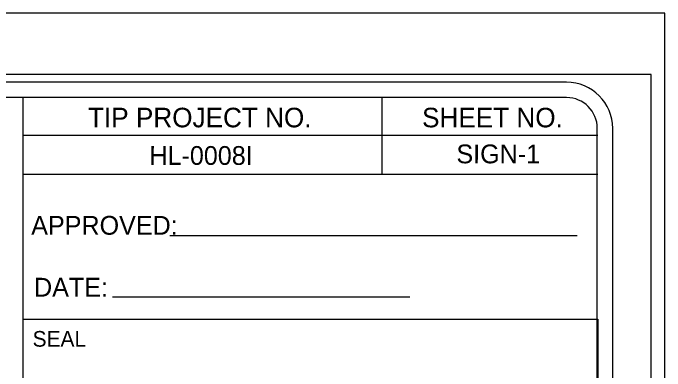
# Model space of a CAD drawing. Extents: x 2046816 to 2049224, y 578750 to 586986.
# Drawn here: x 2049012.1 to 2049224.2, y 586869.4 to 586985.8 of the extents above; entities that cross this region are included whole.
import ezdxf

# ---------------------------------------------------------------- set-up
doc = ezdxf.new("R2010")
doc.units = 0
for name, color, linetype in [('Default', 7, 'Continuous'), ('Old_Level_10', 7, 'Continuous'), ('Old_Level_2', 7, 'Continuous'), ('Old_Level_4', 7, 'Continuous'), ('Sheet Plot Border Inside CELL', 7, 'Continuous'), ('Sheet Plot Border Outside CELL', 7, 'Continuous'), ('Sheet Title CELL', 7, 'Continuous')]:
    doc.layers.add(name, color=color, linetype=linetype)

msp = doc.modelspace()

# ---------------------------------------------------------------- linework, layer by layer
at = {"layer": 'Default'}
for p, q in [((2049015.39, 586933.37), (2049015.39, 586958.31)), ((2049132.11, 586933.36), (2049132.12, 586958.32)), ((2049132.11, 586933.36), (2049132.12, 586958.32)), ((2049015.39, 586946.11), (2049132.12, 586946.1)), ((2049132.12, 586946.1), (2049202.34, 586946.09)), ((2049015.39, 586933.37), (2049202.33, 586933.36)), ((2049063.07, 586913.46), (2049195.65, 586913.46)), ((2049044.39, 586893.55), (2049141.15, 586893.55))]:
    msp.add_line(p, q, dxfattribs=at)
at = {"layer": 'Old_Level_2'}
msp.add_line((2049015.39, 586886.21), (2049015.39, 586933.37), dxfattribs=at)
msp.add_lwpolyline([(2049015.39, 586886.21), (2049202.33, 586886.21), (2049202.33, 586774.83), (2049015.39, 586774.83)], close=True, dxfattribs=at)
at = {"layer": 'Sheet Plot Border Inside CELL'}
msp.add_lwpolyline([(2047553.67, 585910.81), (2049219.66, 585910.81), (2049219.66, 586965.81), (2047553.67, 586965.81)], close=True, dxfattribs=at)
at = {"layer": 'Sheet Plot Border Outside CELL'}
msp.add_lwpolyline([(2049224.17, 586985.81), (2047540.67, 586985.81), (2047540.67, 585890.81), (2049224.17, 585890.81)], close=True, dxfattribs=at)
at = {"layer": 'Sheet Title CELL'}
for points in [[(2049192.16, 586963.31), (2047722.16, 586963.33)], [(2049192.16, 586958.31), (2047772.16, 586958.31)], [(2049202.16, 585928.31), (2049202.16, 586948.31)], [(2049207.16, 585928.31), (2049207.16, 586948.31)]]:
    msp.add_lwpolyline(points, dxfattribs=at)
for radius, end in [(15, 89.9995), (10, 90)]:
    msp.add_arc((2049192.16, 586948.31), radius, 360, end, dxfattribs=at)

# ---------------------------------------------------------------- texts
at = {"layer": 'Default'}
for s, height, p in [('TIP PROJECT NO.', 6.3564, (2049036.45, 586948.65)), ('SHEET NO.', 6.356, (2049145.14, 586948.64)), ('HL-0008I', 6.108, (2049056.43, 586936.43)), ('SIGN-1', 6.108, (2049156.32, 586936.94))]:
    msp.add_text(s, height=height, rotation=359.9949, dxfattribs=at).set_placement(p)
at = {"layer": 'Old_Level_10'}
msp.add_text('SEAL', height=5.093, rotation=359.9949, dxfattribs=at).set_placement((2049018.41, 586877.3))
at = {"layer": 'Old_Level_4'}
for s, p in [('APPROVED:', (2049017.97, 586913.72)), ('DATE:', (2049018.89, 586893.59))]:
    msp.add_text(s, height=6.108, rotation=359.9949, dxfattribs=at).set_placement(p)

doc.saveas('drawing.dxf')
